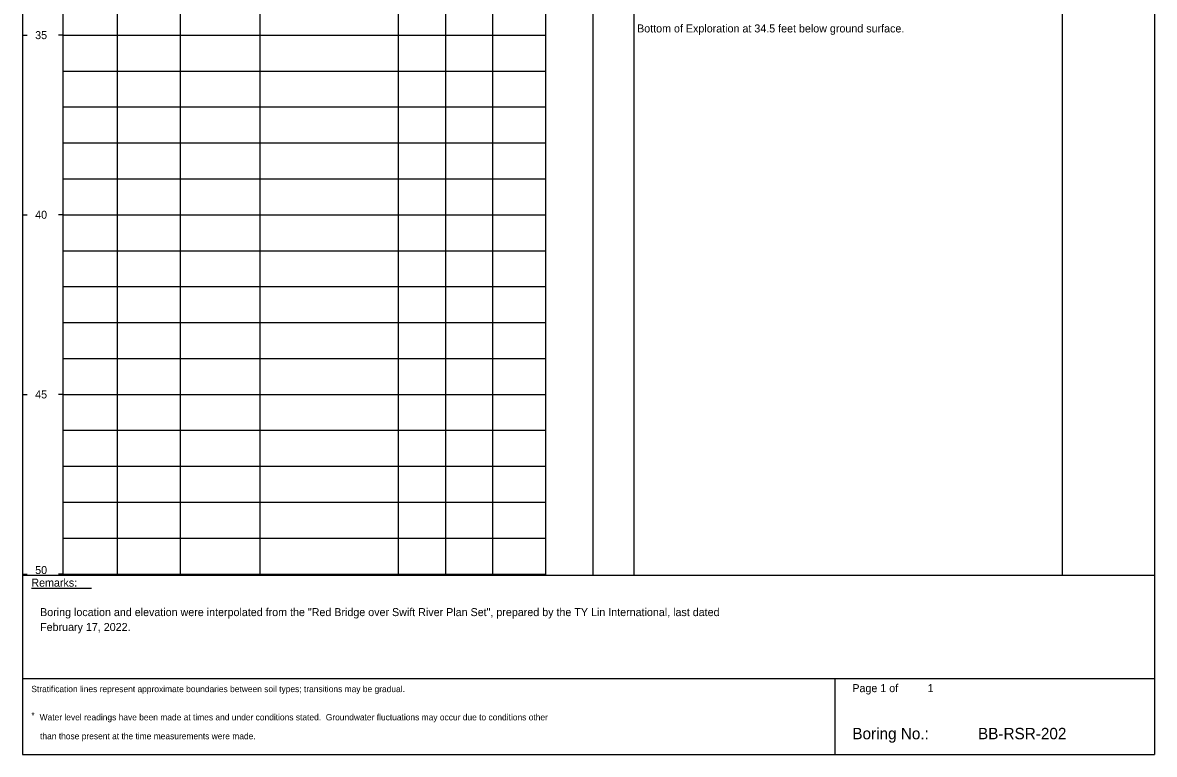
# Model space of a CAD drawing. Extents: x 9419 to 9552, y 6780 to 6865.
# Drawn here: x 9422.45 to 9453.95, y 6791.99 to 6812.36 of the extents above; entities that cross this region are included whole.
import ezdxf

# ---------------------------------------------------------------- set-up
doc = ezdxf.new("R2010")
doc.units = 0
doc.layers.add('7', color=7, linetype='Continuous')

msp = doc.modelspace()

# ---------------------------------------------------------------- linework, layer by layer
at = {"layer": '7'}
msp.add_line((9422.692, 6796.614), (9424.37, 6796.614), dxfattribs=at)
for points in [[(9422.449, 6822.038), (9422.449, 6791.992)], [(9423.567, 6822.038), (9423.567, 6796.983)], [(9425.076, 6822.038), (9425.076, 6796.983)], [(9426.831, 6822.038), (9426.831, 6796.983)], [(9429.046, 6822.038), (9429.046, 6796.983)], [(9432.901, 6822.038), (9432.901, 6796.983)], [(9434.213, 6822.038), (9434.213, 6796.983)], [(9435.526, 6822.038), (9435.526, 6796.983)], [(9437.002, 6822.038), (9437.002, 6796.983)], [(9438.314, 6822.038), (9438.314, 6796.983)], [(9439.463, 6822.038), (9439.463, 6796.983)], [(9451.38, 6822.038), (9451.38, 6796.983)], [(9453.945, 6822.038), (9453.945, 6791.992)], [(9422.449, 6812.011), (9422.571, 6812.011)], [(9423.567, 6812.011), (9423.445, 6812.011)], [(9423.567, 6812.011), (9425.076, 6812.011)], [(9425.076, 6812.011), (9426.831, 6812.011)], [(9426.831, 6812.011), (9429.046, 6812.011)], [(9429.046, 6812.011), (9432.901, 6812.011)], [(9432.901, 6812.011), (9434.213, 6812.011)], [(9434.213, 6812.011), (9435.526, 6812.011)], [(9435.526, 6812.011), (9437.002, 6812.011)], [(9423.567, 6811.011), (9425.076, 6811.011)], [(9425.076, 6811.011), (9426.831, 6811.011)], [(9426.831, 6811.011), (9429.046, 6811.011)], [(9429.046, 6811.011), (9432.901, 6811.011)], [(9432.901, 6811.011), (9434.213, 6811.011)], [(9434.213, 6811.011), (9435.526, 6811.011)], [(9435.526, 6811.011), (9437.002, 6811.011)], [(9423.567, 6810.011), (9425.076, 6810.011)], [(9425.076, 6810.011), (9426.831, 6810.011)], [(9426.831, 6810.011), (9429.046, 6810.011)], [(9429.046, 6810.011), (9432.901, 6810.011)], [(9432.901, 6810.011), (9434.213, 6810.011)], [(9434.213, 6810.011), (9435.526, 6810.011)], [(9435.526, 6810.011), (9437.002, 6810.011)], [(9423.567, 6809.011), (9425.076, 6809.011)], [(9425.076, 6809.011), (9426.831, 6809.011)], [(9426.831, 6809.011), (9429.046, 6809.011)], [(9429.046, 6809.011), (9432.901, 6809.011)], [(9432.901, 6809.011), (9434.213, 6809.011)], [(9434.213, 6809.011), (9435.526, 6809.011)], [(9435.526, 6809.011), (9437.002, 6809.011)], [(9423.567, 6808.011), (9425.076, 6808.011)], [(9425.076, 6808.011), (9426.831, 6808.011)], [(9426.831, 6808.011), (9429.046, 6808.011)], [(9429.046, 6808.011), (9432.901, 6808.011)], [(9432.901, 6808.011), (9434.213, 6808.011)], [(9434.213, 6808.011), (9435.526, 6808.011)], [(9435.526, 6808.011), (9437.002, 6808.011)], [(9422.449, 6807.011), (9422.571, 6807.011)], [(9423.567, 6807.011), (9423.445, 6807.011)], [(9423.567, 6807.011), (9425.076, 6807.011)], [(9425.076, 6807.011), (9426.831, 6807.011)], [(9426.831, 6807.011), (9429.046, 6807.011)], [(9429.046, 6807.011), (9432.901, 6807.011)], [(9432.901, 6807.011), (9434.213, 6807.011)], [(9434.213, 6807.011), (9435.526, 6807.011)], [(9435.526, 6807.011), (9437.002, 6807.011)], [(9423.567, 6806.011), (9425.076, 6806.011)], [(9425.076, 6806.011), (9426.831, 6806.011)], [(9426.831, 6806.011), (9429.046, 6806.011)], [(9429.046, 6806.011), (9432.901, 6806.011)], [(9432.901, 6806.011), (9434.213, 6806.011)], [(9434.213, 6806.011), (9435.526, 6806.011)], [(9435.526, 6806.011), (9437.002, 6806.011)], [(9423.567, 6805.011), (9425.076, 6805.011)], [(9425.076, 6805.011), (9426.831, 6805.011)], [(9426.831, 6805.011), (9429.046, 6805.011)], [(9429.046, 6805.011), (9432.901, 6805.011)], [(9432.901, 6805.011), (9434.213, 6805.011)], [(9434.213, 6805.011), (9435.526, 6805.011)], [(9435.526, 6805.011), (9437.002, 6805.011)], [(9423.567, 6804.011), (9425.076, 6804.011)], [(9425.076, 6804.011), (9426.831, 6804.011)], [(9426.831, 6804.011), (9429.046, 6804.011)], [(9429.046, 6804.011), (9432.901, 6804.011)], [(9432.901, 6804.011), (9434.213, 6804.011)], [(9434.213, 6804.011), (9435.526, 6804.011)], [(9435.526, 6804.011), (9437.002, 6804.011)], [(9423.567, 6803.011), (9425.076, 6803.011)], [(9425.076, 6803.011), (9426.831, 6803.011)], [(9426.831, 6803.011), (9429.046, 6803.011)], [(9429.046, 6803.011), (9432.901, 6803.011)], [(9432.901, 6803.011), (9434.213, 6803.011)], [(9434.213, 6803.011), (9435.526, 6803.011)], [(9435.526, 6803.011), (9437.002, 6803.011)], [(9422.449, 6802.011), (9422.571, 6802.011)], [(9423.567, 6802.011), (9423.445, 6802.011)], [(9423.567, 6802.011), (9425.076, 6802.011)], [(9425.076, 6802.011), (9426.831, 6802.011)], [(9426.831, 6802.011), (9429.046, 6802.011)], [(9429.046, 6802.011), (9432.901, 6802.011)], [(9432.901, 6802.011), (9434.213, 6802.011)], [(9434.213, 6802.011), (9435.526, 6802.011)], [(9435.526, 6802.011), (9437.002, 6802.011)], [(9423.567, 6801.011), (9425.076, 6801.011)], [(9425.076, 6801.011), (9426.831, 6801.011)], [(9426.831, 6801.011), (9429.046, 6801.011)], [(9429.046, 6801.011), (9432.901, 6801.011)], [(9432.901, 6801.011), (9434.213, 6801.011)], [(9434.213, 6801.011), (9435.526, 6801.011)], [(9435.526, 6801.011), (9437.002, 6801.011)], [(9423.567, 6800.011), (9425.076, 6800.011)], [(9425.076, 6800.011), (9426.831, 6800.011)], [(9426.831, 6800.011), (9429.046, 6800.011)], [(9429.046, 6800.011), (9432.901, 6800.011)], [(9432.901, 6800.011), (9434.213, 6800.011)], [(9434.213, 6800.011), (9435.526, 6800.011)], [(9435.526, 6800.011), (9437.002, 6800.011)], [(9423.567, 6799.011), (9425.076, 6799.011)], [(9425.076, 6799.011), (9426.831, 6799.011)], [(9426.831, 6799.011), (9429.046, 6799.011)], [(9429.046, 6799.011), (9432.901, 6799.011)], [(9432.901, 6799.011), (9434.213, 6799.011)], [(9434.213, 6799.011), (9435.526, 6799.011)], [(9435.526, 6799.011), (9437.002, 6799.011)], [(9423.567, 6798.011), (9425.076, 6798.011)], [(9425.076, 6798.011), (9426.831, 6798.011)], [(9426.831, 6798.011), (9429.046, 6798.011)], [(9429.046, 6798.011), (9432.901, 6798.011)], [(9432.901, 6798.011), (9434.213, 6798.011)], [(9434.213, 6798.011), (9435.526, 6798.011)], [(9435.526, 6798.011), (9437.002, 6798.011)], [(9422.449, 6797.011), (9422.571, 6797.011)], [(9422.449, 6796.983), (9453.945, 6796.983)], [(9423.567, 6797.011), (9423.445, 6797.011)], [(9423.567, 6797.011), (9425.076, 6797.011)], [(9425.076, 6797.011), (9426.831, 6797.011)], [(9426.831, 6797.011), (9429.046, 6797.011)], [(9429.046, 6797.011), (9432.901, 6797.011)], [(9432.901, 6797.011), (9434.213, 6797.011)], [(9434.213, 6797.011), (9435.526, 6797.011)], [(9435.526, 6797.011), (9437.002, 6797.011)], [(9422.449, 6794.1), (9453.945, 6794.1)], [(9445.053, 6794.1), (9445.053, 6791.992)], [(9422.449, 6791.992), (9453.945, 6791.992)]]:
    msp.add_lwpolyline(points, dxfattribs=at)

# ---------------------------------------------------------------- texts
for s, height, p in [('Bottom of Exploration at 34.5 feet below ground surface.', 0.2228, (9439.55, 6812.085)), ('35', 0.2228, (9422.798, 6811.899)), ('40', 0.2228, (9422.798, 6806.899)), ('45', 0.2228, (9422.798, 6801.899)), ('50', 0.2228, (9422.798, 6797.011)), ('Remarks:', 0.2228, (9422.692, 6796.66)), ('Boring location and elevation were interpolated from the "Red Bridge over Swift River Plan Set", prepared by the TY Lin International, last dated', 0.222801, (9422.935, 6795.84)), ('February 17, 2022.', 0.2228, (9422.935, 6795.425)), ('Stratification lines represent approximate boundaries between soil types; transitions may be gradual.', 0.175058, (9422.692, 6793.724)), ('Page 1 of ', 0.2228, (9445.54, 6793.724)), ('1', 0.223, (9447.636, 6793.724)), ('*', 0.175, (9422.692, 6792.987)), (' Water level readings have been made at times and under conditions stated.  Groundwater fluctuations may occur due to conditions other', 0.175058, (9422.857, 6792.938)), ('Boring No.:', 0.31829, (9445.54, 6792.412)), ('than those present at the time measurements were made.', 0.17506, (9422.935, 6792.412)), ('BB-RSR-202', 0.3183, (9449.037, 6792.412))]:
    msp.add_text(s, height=height, dxfattribs=at).set_placement(p)

doc.saveas('drawing.dxf')
